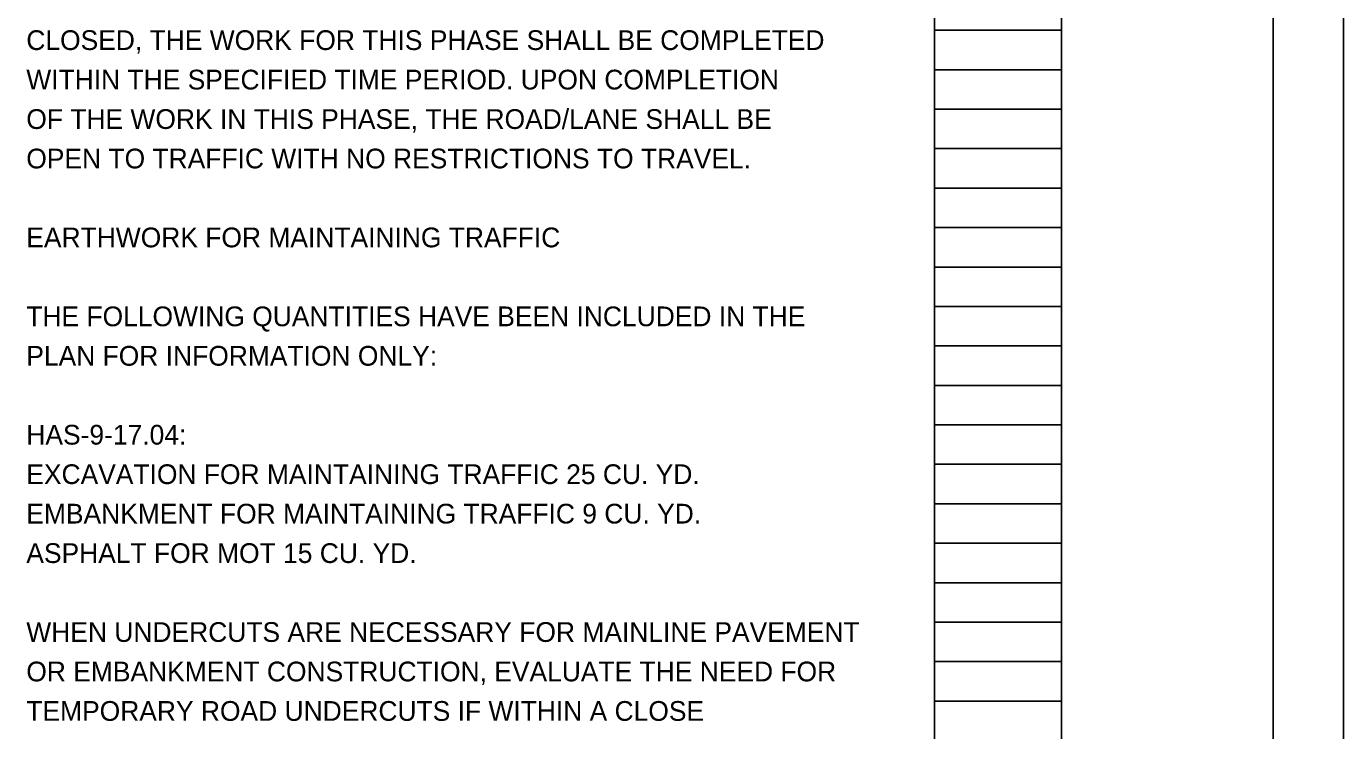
# Model space of a CAD drawing. Extents: x -50 to 112, y -27 to 22.
# Drawn here: x 102.66 to 112, y 5.25 to 10.25 of the extents above; entities that cross this region are included whole.
import ezdxf

# ---------------------------------------------------------------- set-up
doc = ezdxf.new("R2010")
doc.units = 0
for name, color, linetype in [('SC_Scratch1', 7, 'Continuous'), ('SH_Border', 7, 'Continuous'), ('SH_Cut_Line', 7, 'Continuous'), ('SH_Text', 7, 'Continuous')]:
    doc.layers.add(name, color=color, linetype=linetype)

msp = doc.modelspace()

# ---------------------------------------------------------------- linework, layer by layer
at = {"layer": 'SC_Scratch1'}
for p, q in [((109.1, 0.98), (109.1, 21.14)), ((110, 0.98), (110, 21.14)), ((109.1, 10.22), (110, 10.22)), ((109.1, 9.94), (110, 9.94)), ((109.1, 9.66), (110, 9.66)), ((109.1, 9.38), (110, 9.38)), ((109.1, 9.1), (110, 9.1)), ((109.1, 8.82), (110, 8.82)), ((109.1, 8.54), (110, 8.54)), ((109.1, 8.26), (110, 8.26)), ((109.1, 7.98), (110, 7.98)), ((109.1, 7.7), (110, 7.7)), ((109.1, 7.42), (110, 7.42)), ((109.1, 7.14), (110, 7.14)), ((109.1, 6.86), (110, 6.86)), ((109.1, 6.58), (110, 6.58)), ((109.1, 6.3), (110, 6.3)), ((109.1, 6.02), (110, 6.02)), ((109.1, 5.74), (110, 5.74)), ((109.1, 5.46), (110, 5.46))]:
    msp.add_line(p, q, dxfattribs=at)
at = {"layer": 'SH_Border'}
msp.add_line((110, 0.5), (110, 21.5), dxfattribs=at)
msp.add_lwpolyline([(79.5, 21.5), (111.5, 21.5), (111.5, 0.5), (79.5, 0.5)], close=True, dxfattribs=at)
at = {"layer": 'SH_Cut_Line'}
msp.add_lwpolyline([(78, 0), (112, 0), (112, 22), (78, 22)], close=True, dxfattribs=at)

# ---------------------------------------------------------------- texts
at = {"layer": 'SH_Text'}
for s, p in [('CLOSED, THE WORK FOR THIS PHASE SHALL BE COMPLETED ', (102.66, 10.08)), ('WITHIN THE SPECIFIED TIME PERIOD. UPON COMPLETION ', (102.66, 9.8)), ('OF THE WORK IN THIS PHASE, THE ROAD/LANE SHALL BE ', (102.66, 9.52)), ('OPEN TO TRAFFIC WITH NO RESTRICTIONS TO TRAVEL.', (102.66, 9.24)), ('EARTHWORK FOR MAINTAINING TRAFFIC', (102.66, 8.68)), ('THE FOLLOWING QUANTITIES HAVE BEEN INCLUDED IN THE ', (102.66, 8.12)), ('PLAN FOR INFORMATION ONLY:', (102.66, 7.84)), ('HAS-9-17.04:', (102.66, 7.28)), ('EXCAVATION FOR MAINTAINING TRAFFIC 25 CU. YD.', (102.66, 7)), ('EMBANKMENT FOR MAINTAINING TRAFFIC 9 CU. YD.', (102.66, 6.72)), ('ASPHALT FOR MOT 15 CU. YD.', (102.66, 6.44)), ('WHEN UNDERCUTS ARE NECESSARY FOR MAINLINE PAVEMENT', (102.66, 5.88)), ('OR EMBANKMENT CONSTRUCTION, EVALUATE THE NEED FOR', (102.66, 5.6)), ('TEMPORARY ROAD UNDERCUTS IF WITHIN A CLOSE ', (102.66, 5.32))]:
    msp.add_text(s, height=0.14, dxfattribs=at).set_placement(p)

doc.saveas('drawing.dxf')
